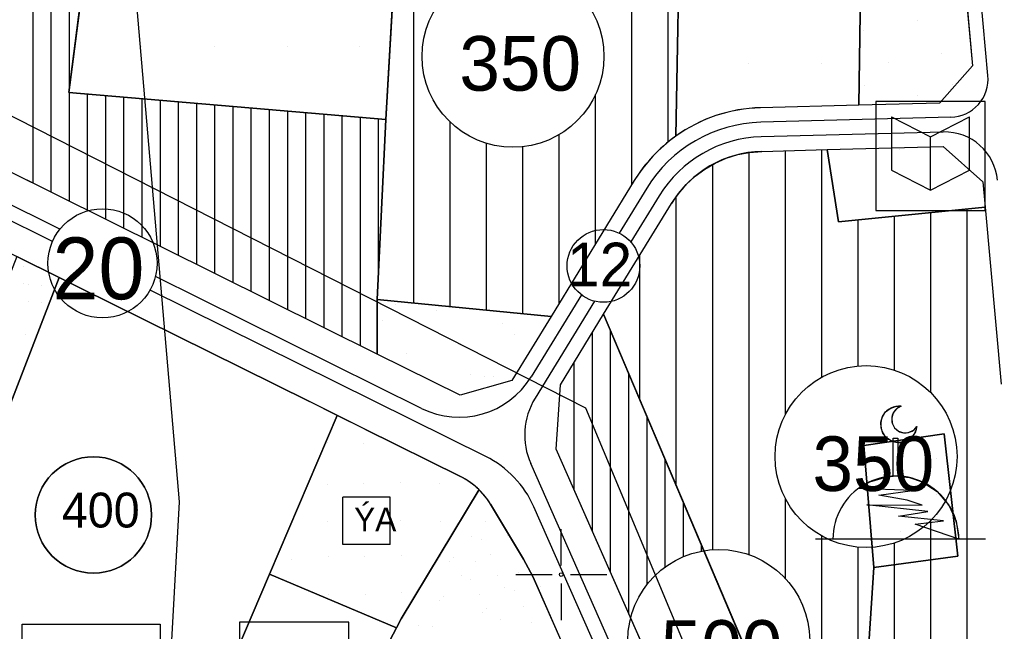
# Model space of a CAD drawing. Extents: x 419109 to 421295, y 4452223 to 4457798.
# Drawn here: x 420351.1 to 420619.9, y 4452484.4 to 4452652.5 of the extents above; entities that cross this region are included whole.
import ezdxf

# ---------------------------------------------------------------- set-up
doc = ezdxf.new("R2010")
doc.units = 0
for name, color, linetype in [('ADA', 7, 'Continuous'), ('ADAKENARI', 7, 'Continuous'), ('Default', 7, 'Continuous'), ('KALDIRIM', 7, 'Continuous'), ('KD_DAIRE', 7, 'Continuous'), ('KD_YGEN', 7, 'Continuous'), ('LJ_SEMBOL', 7, 'Continuous'), ('PAFTALAMA', 7, 'Continuous'), ('PL_AYA_PARK_DINLENME', 7, 'Continuous'), ('PL_KON_MEV_350', 7, 'Continuous'), ('PL_KON_MEV_450', 7, 'Continuous'), ('PL_KON_MEV_500', 7, 'Continuous'), ('PL_OZEL_DONATI', 7, 'Continuous'), ('PL_SAY_DINI_TESIS', 7, 'Continuous'), ('PL_SAY_ILKOGRETIM', 7, 'Continuous'), ('PL_SAY_KULTUR_TESIS', 7, 'Continuous'), ('PL_TİCK', 7, 'Continuous'), ('SM_DAIRE', 7, 'Continuous'), ('SM_SEMBOL', 7, 'Continuous'), ('SM_TAKS', 7, 'Continuous'), ('SN_3_DERECE_KAYNAK_KORUMA', 7, 'Continuous'), ('SN_KENTSEL_DONUSUM', 7, 'Continuous'), ('TR_DINITESIS', 7, 'Continuous'), ('TR_ILKEGITIM', 7, 'Continuous'), ('TR_KULTURELTESIS', 7, 'Continuous'), ('TR_ORTAYOGUNKONUT', 7, 'Continuous'), ('TR_PARKALANI', 7, 'Continuous'), ('TR_SAGLIKTESIS', 7, 'Continuous'), ('TR_TİCK', 7, 'Continuous'), ('TR_YUKSEKYOGUNKONUT', 7, 'Continuous')]:
    doc.layers.add(name, color=color, linetype=linetype)

# ---------------------------------------------------------------- blocks, each defined once
blk = doc.blocks.new('POINT_DISPLAY')
at = {"layer": 'Default'}
blk.add_line((0, 0), (0, 0), dxfattribs=at)

msp = doc.modelspace()

# ---------------------------------------------------------------- linework, layer by layer
at = {"layer": 'ADA'}
for p, q in [((420376.66, 4452726.13), (420364.66, 4452632.46)), ((420451.75, 4452625.1), (420455.62, 4452691.68)), ((420532.64, 4452685.1), (420531.45, 4452620.49)), ((420581.77, 4452629.03), (420582.63, 4452685.79)), ((420364.66, 4452632.46), (420451.75, 4452625.1)), ((420451.75, 4452625.1), (420449.42, 4452575.56)), ((420573.09, 4452616.8), (420576.19, 4452596.92)), ((420576.19, 4452596.92), (420616.56, 4452601)), ((420344.45, 4452590.34), (420367.8, 4452578.76)), ((420333.09, 4452507.03), (420361.98, 4452581.65)), ((420449.42, 4452575.56), (420497.19, 4452570.95)), ((420449.42, 4452560.62), (420449.42, 4452575.56)), ((420553.65, 4452472.53), (420511.62, 4452571.53)), ((420446, 4452539.98), (420430.76, 4452547.54)), ((420438.38, 4452543.76), (420401.24, 4452456.66)), ((420605.26, 4452538.64), (420583.2, 4452535.51)), ((420608.99, 4452505.09), (420605.26, 4452538.64)), ((420583.2, 4452535.51), (420585.88, 4452501.96)), ((420477.38, 4452523.34), (420456, 4452487.81)), ((420585.88, 4452501.96), (420608.99, 4452505.09)), ((420454.71, 4452485.36), (420419.76, 4452500.1)), ((420456, 4452487.81), (420435.44, 4452448.79))]:
    msp.add_line(p, q, dxfattribs=at)
msp.add_arc((420463.41, 4452509.02), 20, 30.9491, 63.6203, dxfattribs=at)
at = {"layer": 'ADAKENARI'}
for p, q in [((420609.16, 4452682.74), (420613.04, 4452639.84)), ((420361.09, 4452604.42), (420282.55, 4452643.37)), ((420613.04, 4452639.84), (420603.95, 4452629.61)), ((420581.77, 4452629.03), (420554.77, 4452628.32)), ((420603.95, 4452629.61), (420581.77, 4452629.03)), ((420573.09, 4452616.8), (420605.03, 4452617.64)), ((420605.03, 4452617.64), (420615.93, 4452607.94)), ((420555.09, 4452616.32), (420573.09, 4452616.8)), ((420520.07, 4452608.28), (420497.19, 4452570.95)), ((420615.93, 4452607.94), (420616.56, 4452601)), ((420449.42, 4452560.62), (420361.09, 4452604.42)), ((420511.62, 4452571.53), (420530.3, 4452602.01)), ((420616.56, 4452601), (420620.97, 4452552.31)), ((420367.8, 4452578.76), (420412.06, 4452556.81)), ((420497.19, 4452570.95), (420486.43, 4452553.38)), ((420499.75, 4452552.17), (420511.62, 4452571.53)), ((420472.24, 4452549.3), (420449.42, 4452560.62)), ((420412.06, 4452556.81), (420430.76, 4452547.54)), ((420486.43, 4452553.38), (420472.24, 4452549.3)), ((420498.57, 4452534.49), (420499.75, 4452552.17)), ((420446, 4452539.98), (420472.3, 4452526.94)), ((420569.99, 4452372.88), (420498.57, 4452534.49)), ((420480.57, 4452519.3), (420489.63, 4452504.19)), ((420489.63, 4452504.19), (420490.93, 4452501.84)), ((420490.93, 4452501.84), (420492.14, 4452499.45)), ((420492.14, 4452499.45), (420493.27, 4452497.02)), ((420493.27, 4452497.02), (420502.09, 4452477.06))]:
    msp.add_line(p, q, dxfattribs=at)
for radius, start, end in [(42, 91.5128, 125.5707), (42, 125.5707, 148.4977), (30, 91.5128, 148.4977)]:
    msp.add_arc((420555.88, 4452586.33), radius, start, end, dxfattribs=at)
at = {"layer": 'KALDIRIM'}
for p, q in [((420617.3, 4452637.2), (420613.16, 4452682.89)), ((420362.19, 4452594.94), (420278.83, 4452636.28)), ((420360.12, 4452591.51), (420277.07, 4452632.69)), ((420360.12, 4452591.51), (420278.42, 4452632.02)), ((420607.07, 4452625.7), (420554.87, 4452624.32)), ((420605.01, 4452621.64), (420554.98, 4452620.32)), ((420523.48, 4452606.19), (420515.92, 4452593.85)), ((420526.89, 4452604.1), (420519.12, 4452591.42)), ((420461.55, 4452545.67), (420388.44, 4452581.93)), ((420479.27, 4452532.42), (420386.96, 4452578.2)), ((420505.52, 4452576.89), (420491.71, 4452554.35)), ((420509.14, 4452575.14), (420492.8, 4452548.47)), ((420532.87, 4452437.08), (420491.59, 4452530.5)), ((420529.24, 4452435.4), (420492.46, 4452518.63))]:
    msp.add_line(p, q, dxfattribs=at)
for centre, radius, start, end in [((420606.79, 4452636.24), 10.55, 271.5128, 5.172), ((420555.88, 4452586.33), 38, 91.5128, 148.4977), ((420555.88, 4452586.33), 34, 91.5128, 148.4977), ((420605.4, 4452607.08), 14.57, 5.172, 91.5128), ((420471.89, 4452566.5), 23.25, 243.6241, 328.4977), ((420509.33, 4452538.33), 19.39, 148.4977, 203.8418), ((420466.81, 4452507.3), 28.04, 23.8418, 63.6241)]:
    msp.add_arc(centre, radius, start, end, dxfattribs=at)
at = {"layer": 'KD_DAIRE'}
for centre, radius in [((420373.88, 4452585.55), 15), ((420511.6, 4452584.83), 10)]:
    msp.add_circle(centre, radius, dxfattribs=at)
at = {"layer": 'LJ_SEMBOL'}
for p, q in [((420616.5, 4452630.06), (420586.5, 4452630.06)), ((420586.5, 4452630.06), (420586.5, 4452600.06)), ((420616.5, 4452600.06), (420616.5, 4452630.06)), ((420590.81, 4452625.77), (420590.81, 4452611.11)), ((420590.81, 4452625.77), (420601.5, 4452620.33)), ((420601.5, 4452620.33), (420612.19, 4452625.77)), ((420612.19, 4452611.11), (420612.19, 4452625.77)), ((420601.5, 4452605.66), (420601.5, 4452620.33)), ((420590.81, 4452611.11), (420601.5, 4452605.66)), ((420601.5, 4452605.66), (420612.19, 4452611.11)), ((420586.5, 4452600.06), (420616.5, 4452600.06)), ((420616.59, 4452509.74), (420569.93, 4452509.74))]:
    msp.add_line(p, q, dxfattribs=at)
for points in [[(420586.5, 4452600.06), (420616.5, 4452600.06), (420616.5, 4452630.06), (420586.5, 4452630.06)], [(420597.77, 4452540.7), (420597.35, 4452539.2), (420596.48, 4452537.89), (420595.25, 4452536.92), (420593.78, 4452536.38), (420592.21, 4452536.32), (420590.7, 4452536.75), (420589.4, 4452537.62), (420588.44, 4452538.86), (420587.9, 4452540.33), (420587.84, 4452541.89), (420588.27, 4452543.4), (420589.15, 4452544.7), (420590.39, 4452545.66), (420591.86, 4452546.2), (420593.43, 4452546.25), (420592.17, 4452545.55), (420591.27, 4452544.44), (420590.85, 4452543.07), (420590.98, 4452541.64), (420591.63, 4452540.37), (420592.72, 4452539.43), (420594.07, 4452538.97), (420595.5, 4452539.04), (420596.8, 4452539.65)], [(420609.29, 4452509.75), (420597.31, 4452513.81), (420605.1, 4452514.72), (420592.66, 4452516.03), (420600.75, 4452517.29), (420584, 4452519.18), (420599.25, 4452519.1), (420595.08, 4452520.42), (420587.3, 4452521.85), (420596.52, 4452523.1), (420581.63, 4452523.62), (420584.8, 4452525.5), (420589.52, 4452526.88), (420591.27, 4452527.05), (420591.27, 4452537.46), (420592.52, 4452537.46), (420592.52, 4452527.05), (420595.76, 4452526.64), (420599.17, 4452525.5), (420603.32, 4452522.83), (420606.54, 4452519.11), (420608.59, 4452514.63)], [(420351.83, 4452486.39), (420389.76, 4452486.39), (420389.76, 4452457.46), (420351.83, 4452457.46)], [(420411.55, 4452456.89), (420441.55, 4452456.89), (420441.55, 4452486.89), (420411.55, 4452486.89)]]:
    msp.add_lwpolyline(points, close=True, dxfattribs=at)
for centre, radius, start, end in [((420592.81, 4452541.29), 5, 82.8556, 353.3219), ((420594.58, 4452542.68), 3.75, 107.9671, 328.2104), ((420591.98, 4452509.75), 17.31, 359.967, 180)]:
    msp.add_arc(centre, radius, start, end, dxfattribs=at)
at = {"layer": 'PAFTALAMA'}
for p, q in [((420500, 4452502.5), (420500, 4452512.5)), ((420487.5, 4452500), (420497.5, 4452500)), ((420502.5, 4452500), (420512.5, 4452500)), ((420500, 4452497.5), (420500, 4452487.5))]:
    msp.add_line(p, q, dxfattribs=at)
msp.add_circle((420500, 4452500), 0.5, dxfattribs=at)
at = {"layer": 'PL_AYA_PARK_DINLENME'}
for points in [[(420609.16, 4452682.74), (420613.04, 4452639.84), (420603.95, 4452629.61), (420581.77, 4452629.03), (420582.63, 4452685.79)], [(420449.42, 4452575.56), (420497.19, 4452570.95), (420486.43, 4452553.38), (420472.24, 4452549.3), (420449.42, 4452560.62)]]:
    msp.add_lwpolyline(points, close=True, dxfattribs=at)
for points in [[(420264.82, 4452450.42), (420276.25, 4452443.66), (420320.59, 4452492), (420333.09, 4452507.03), (420361.98, 4452581.65), (420350.28, 4452587.45), (420350.28, 4452587.45), (420321.86, 4452514.01), (420315.23, 4452506.09), (420308.58, 4452498.14), (420264.82, 4452450.42)], [(420477.38, 4452523.34), (420456, 4452487.81), (420454.71, 4452485.36), (420435.44, 4452448.79), (420430.68, 4452439.74), (420426.62, 4452432.05), (420521.98, 4452432.05), (420521.98, 4452432.05), (420508.96, 4452461.5), (420502.09, 4452477.06), (420493.27, 4452497.02), (420492.14, 4452499.45), (420490.93, 4452501.84), (420489.63, 4452504.19), (420480.57, 4452519.3)]]:
    msp.add_lwpolyline(points, dxfattribs=at)
msp.add_arc((420463.41, 4452509.02), 20, 30.9491, 45.7214, dxfattribs=at)
at = {"layer": 'PL_KON_MEV_350'}
msp.add_lwpolyline([(420520.07, 4452608.28), (420497.19, 4452570.95), (420449.42, 4452575.56), (420451.75, 4452625.1), (420455.62, 4452691.68), (420520.57, 4452686.13), (420532.64, 4452685.1), (420531.45, 4452620.49), (420529.77, 4452619.23), (420528.16, 4452617.88), (420526.61, 4452616.46), (420525.14, 4452614.96), (420523.75, 4452613.38), (420522.44, 4452611.74), (420521.21, 4452610.04)], close=True, dxfattribs=at)
for points in [[(420553.65, 4452472.53), (420511.62, 4452571.53), (420530.3, 4452602.01), (420532.18, 4452604.73), (420534.36, 4452607.23), (420536.79, 4452609.48), (420539.46, 4452611.44), (420542.33, 4452613.1), (420545.37, 4452614.43), (420548.53, 4452615.42), (420551.78, 4452616.05), (420555.09, 4452616.32), (420573.09, 4452616.8), (420576.19, 4452596.92), (420616.56, 4452601), (420620.97, 4452552.31)], [(420584.26, 4452476.75), (420585.88, 4452501.96), (420608.99, 4452505.09), (420605.26, 4452538.64), (420583.2, 4452535.51), (420585.88, 4452501.96), (420584.26, 4452476.75)]]:
    msp.add_lwpolyline(points, dxfattribs=at)
at = {"layer": 'PL_KON_MEV_450'}
msp.add_lwpolyline([(420299.79, 4452788.55), (420467.87, 4452834.02), (420464.63, 4452792.44), (420385.14, 4452799.11), (420376.66, 4452726.13), (420364.66, 4452632.46), (420451.75, 4452625.1), (420449.42, 4452575.56), (420449.42, 4452560.62), (420361.09, 4452604.42), (420282.55, 4452643.37), (420274.78, 4452657.74), (420288.95, 4452776.01)], close=True, dxfattribs=at)
at = {"layer": 'PL_KON_MEV_500'}
msp.add_lwpolyline([(420569.99, 4452372.88), (420498.57, 4452534.49), (420499.75, 4452552.17), (420511.62, 4452571.53), (420553.65, 4452472.53), (420592.92, 4452383.64)], close=True, dxfattribs=at)
at = {"layer": 'PL_OZEL_DONATI'}
msp.add_lwpolyline([(420532.64, 4452685.1), (420554.32, 4452686.65), (420582.63, 4452685.79), (420581.77, 4452629.03), (420554.77, 4452628.32), (420551.66, 4452628.12), (420548.57, 4452627.69), (420545.52, 4452627.03), (420542.52, 4452626.15), (420539.6, 4452625.05), (420536.77, 4452623.73), (420534.05, 4452622.21), (420531.45, 4452620.49)], close=True, dxfattribs=at)
at = {"layer": 'PL_SAY_DINI_TESIS'}
msp.add_lwpolyline([(420472.3, 4452526.94), (420446, 4452539.98), (420438.38, 4452543.76), (420419.76, 4452500.1), (420454.71, 4452485.36), (420456, 4452487.81), (420477.38, 4452523.34)], dxfattribs=at)
msp.add_lwpolyline([(420585.88, 4452501.96), (420583.2, 4452535.51), (420605.26, 4452538.64), (420608.99, 4452505.09)], close=True, dxfattribs=at)
msp.add_arc((420463.41, 4452509.02), 20, 45.7214, 63.6203, dxfattribs=at)
at = {"layer": 'PL_SAY_ILKOGRETIM'}
msp.add_lwpolyline([(420364.66, 4452632.46), (420376.66, 4452726.13), (420457.13, 4452717.64), (420455.62, 4452691.68), (420451.75, 4452625.1)], close=True, dxfattribs=at)
at = {"layer": 'PL_SAY_KULTUR_TESIS'}
msp.add_lwpolyline([(420616.56, 4452601), (420576.19, 4452596.92), (420573.09, 4452616.8), (420605.03, 4452617.64), (420615.93, 4452607.94)], close=True, dxfattribs=at)
msp.add_lwpolyline([(420454.71, 4452485.36), (420419.76, 4452500.1), (420401.24, 4452456.66), (420430.68, 4452439.74), (420435.44, 4452448.79), (420454.71, 4452485.36)], dxfattribs=at)
at = {"layer": 'PL_TİCK'}
msp.add_lwpolyline([(420276.25, 4452443.66), (420281.87, 4452440.33), (420366.31, 4452390.34), (420401.24, 4452456.66), (420419.76, 4452500.1), (420438.38, 4452543.76), (420430.76, 4452547.54), (420412.06, 4452556.81), (420367.8, 4452578.76), (420361.98, 4452581.65), (420333.09, 4452507.03), (420320.59, 4452492), (420276.25, 4452443.66)], dxfattribs=at)
at = {"layer": 'SM_DAIRE'}
for centre in [(420486.72, 4452642.44), (420583.79, 4452532.43), (420543.3, 4452481.88)]:
    msp.add_circle(centre, 25, dxfattribs=at)
at = {"layer": 'SM_SEMBOL'}
for points in [[(420452.93, 4452521.26), (420439.93, 4452521.26)], [(420439.93, 4452508.26), (420439.93, 4452521.26)], [(420452.93, 4452508.26), (420452.93, 4452521.26)], [(420452.93, 4452508.26), (420439.93, 4452508.26)]]:
    msp.add_lwpolyline(points, dxfattribs=at)
at = {"layer": 'SM_TAKS'}
msp.add_circle((420371.38, 4452516.37), 15.99, dxfattribs=at)
at = {"layer": 'SN_3_DERECE_KAYNAK_KORUMA'}
msp.add_lwpolyline([(420357.81, 4452232.59), (420364.57, 4452258.77), (420388.14, 4452395.87), (420395.04, 4452520.02), (420383.4, 4452655.62), (420344.11, 4452773.22), (420290.77, 4452875.07), (420213.22, 4452980.45), (420010.57, 4453225.26), (419772.92, 4453473.96), (419554.68, 4453657.1), (419332.55, 4453805.23), (419159.82, 4453894.89), (419126.5, 4453906.07)], dxfattribs=at)
at = {"layer": 'SN_KENTSEL_DONUSUM'}
for p, q in [((420285.4, 4452658.29), (420506.7, 4452545.79)), ((420506.7, 4452545.79), (420589.68, 4452346.63))]:
    msp.add_line(p, q, dxfattribs=at)
at = {"layer": 'TR_ORTAYOGUNKONUT'}
for p, q in [((420459.42, 4452574.59), (420459.42, 4452691.35)), ((420519.42, 4452607.22), (420519.42, 4452686.23)), ((420529.42, 4452618.94), (420529.42, 4452685.37)), ((420509.42, 4452590.91), (420509.42, 4452631.99)), ((420469.42, 4452573.63), (420469.42, 4452624.39)), ((420499.42, 4452574.59), (420499.42, 4452620.91)), ((420479.42, 4452572.66), (420479.42, 4452618.53)), ((420489.42, 4452571.7), (420489.42, 4452617.59)), ((420551.62, 4452505.45), (420551.62, 4452616.02)), ((420561.62, 4452543.99), (420561.62, 4452616.49)), ((420571.62, 4452554.27), (420571.62, 4452616.76)), ((420541.62, 4452506.83), (420541.62, 4452612.69)), ((420531.62, 4452524.42), (420531.62, 4452603.92)), ((420601.62, 4452549.95), (420601.62, 4452599.49)), ((420611.62, 4452392.41), (420611.62, 4452600.5)), ((420581.62, 4452557.33), (420581.62, 4452597.47)), ((420591.62, 4452556.17), (420591.62, 4452598.48)), ((420521.62, 4452547.98), (420521.62, 4452587.85)), ((420561.62, 4452498.89), (420561.62, 4452520.86)), ((420601.62, 4452404.62), (420601.62, 4452514.91)), ((420571.62, 4452475), (420571.62, 4452510.59)), ((420581.62, 4452476.38), (420581.62, 4452507.52)), ((420591.62, 4452446.16), (420591.62, 4452508.69))]:
    msp.add_line(p, q, dxfattribs=at)
at = {"layer": 'TR_TİCK'}
for points in [[(420361.98, 4452581.65), (420333.09, 4452507.03), (420320.59, 4452492), (420276.25, 4452443.66), (420281.87, 4452440.33), (420366.31, 4452390.34), (420401.24, 4452456.66), (420419.76, 4452500.1), (420438.38, 4452543.76), (420430.76, 4452547.54), (420412.06, 4452556.81), (420367.8, 4452578.76), (420361.98, 4452581.65)], [(420351.83, 4452457.46), (420351.83, 4452486.39), (420389.76, 4452486.39), (420389.76, 4452457.46), (420351.83, 4452457.46)]]:
    msp.add_lwpolyline(points, dxfattribs=at)
for start, end in [(0, 180), (180, 0)]:
    msp.add_arc((420371.38, 4452516.37), 15.99, start, end, dxfattribs=at)
at = {"layer": 'TR_YUKSEKYOGUNKONUT'}
for p, q in [((420364.78, 4452633.41), (420364.78, 4452806.13)), ((420354.78, 4452607.55), (420354.78, 4452803.43)), ((420359.78, 4452605.07), (420359.78, 4452804.78)), ((420364.78, 4452602.59), (420364.78, 4452632.45)), ((420369.78, 4452600.11), (420369.78, 4452632.02)), ((420374.78, 4452597.63), (420374.78, 4452631.6)), ((420379.78, 4452595.15), (420379.78, 4452631.18)), ((420384.78, 4452592.67), (420384.78, 4452630.76)), ((420389.78, 4452590.19), (420389.78, 4452630.33)), ((420394.78, 4452587.71), (420394.78, 4452629.91)), ((420399.78, 4452585.23), (420399.78, 4452629.49)), ((420404.78, 4452582.75), (420404.78, 4452629.07)), ((420409.78, 4452580.27), (420409.78, 4452628.65)), ((420414.78, 4452577.8), (420414.78, 4452628.22)), ((420419.78, 4452575.32), (420419.78, 4452627.8)), ((420424.78, 4452572.84), (420424.78, 4452627.38)), ((420429.78, 4452570.36), (420429.78, 4452626.96)), ((420434.78, 4452567.88), (420434.78, 4452626.53)), ((420439.78, 4452565.4), (420439.78, 4452626.11)), ((420444.78, 4452562.92), (420444.78, 4452625.69)), ((420449.78, 4452583.13), (420449.78, 4452625.27)), ((420508.57, 4452511.87), (420508.57, 4452566.55)), ((420513.57, 4452500.55), (420513.57, 4452566.95)), ((420503.57, 4452523.18), (420503.57, 4452558.39)), ((420518.57, 4452489.24), (420518.57, 4452555.17)), ((420523.57, 4452497.24), (420523.57, 4452543.39)), ((420528.57, 4452502.09), (420528.57, 4452531.61)), ((420533.57, 4452504.91), (420533.57, 4452519.83)), ((420538.57, 4452506.43), (420538.57, 4452508.06))]:
    msp.add_line(p, q, dxfattribs=at)

# ---------------------------------------------------------------- block references
at = {"layer": 'TR_DINITESIS', "xscale": 0.1, "yscale": 0.10000000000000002}
for p in [(420435.74, 4452536.3), (420445.5, 4452536.11), (420593.2, 4452531.96), (420603.2, 4452531.96), (420435.74, 4452524.84), (420445.5, 4452524.93), (420455.83, 4452525.21), (420466.48, 4452525.09), (420593.2, 4452521.96), (420603.2, 4452521.96), (420435.74, 4452514.5), (420445.88, 4452514.5), (420455.83, 4452514.98), (420466.86, 4452514.67), (420593.2, 4452511.96), (420603.2, 4452511.96), (420436.06, 4452504.83), (420445.83, 4452504.93), (420456.16, 4452505.21), (420466.8, 4452505.09), (420425.81, 4452504.01), (420436.12, 4452494.59), (420446.26, 4452494.59), (420456.21, 4452495.07)]:
    msp.add_blockref('POINT_DISPLAY', p, dxfattribs=at)
at = {"layer": 'TR_ILKEGITIM', "xscale": 0.1, "yscale": 0.10000000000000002}
for p in [(420384.66, 4452645.1), (420404.66, 4452645.1), (420424.66, 4452645.1), (420444.66, 4452645.1)]:
    msp.add_blockref('POINT_DISPLAY', p, dxfattribs=at)
at = {"layer": 'TR_KULTURELTESIS', "xscale": 0.1, "yscale": 0.10000000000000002}
msp.add_blockref('POINT_DISPLAY', (420593.09, 4452616.92), dxfattribs=at)
at = {"layer": 'TR_PARKALANI', "xscale": 0.1, "yscale": 0.10000000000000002}
for p in [(420597.99, 4452652.2), (420583.22, 4452649.59), (420604.65, 4452643.22), (420589.88, 4452640.61), (420583.29, 4452634.33), (420607.42, 4452634.71), (420598.06, 4452631.73), (420352.28, 4452584.65), (420352.28, 4452580.06), (420353.45, 4452579.75), (420357.2, 4452579.41), (420353.45, 4452575.16), (420357.2, 4452574.82), (420454.42, 4452574.3), (420465.65, 4452572.47), (420450.87, 4452569.86), (420483.97, 4452569.09), (420352.61, 4452566.06), (420487.08, 4452566.09), (420472.31, 4452563.49), (420457.54, 4452560.88), (420475.08, 4452554.98), (420478.97, 4452554.51), (420481.36, 4452554.32), (420479.21, 4452514.58), (420475.34, 4452510.53), (420485.35, 4452510.71), (420477.98, 4452509.66), (420470.41, 4452504.76), (420480.46, 4452505.44), (420469.33, 4452503.64), (420476.39, 4452503.67), (420472.52, 4452499.62), (420482.53, 4452499.8), (420488.24, 4452500.48), (420475.16, 4452498.75), (420494.38, 4452496.61), (420477.64, 4452494.54), (420484.36, 4452496.43), (420487.01, 4452495.56), (420466.51, 4452492.74), (420467.58, 4452493.85), (420489.49, 4452491.34), (420478.36, 4452489.54), (420479.43, 4452490.65), (420460.87, 4452485.97), (420483.28, 4452487.77), (420491.71, 4452486.72), (420464.62, 4452485.63)]:
    msp.add_blockref('POINT_DISPLAY', p, dxfattribs=at)
at = {"layer": 'TR_SAGLIKTESIS', "xscale": 0.1, "yscale": 0.10000000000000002}
for p in [(420551.45, 4452640.49), (420571.45, 4452640.49)]:
    msp.add_blockref('POINT_DISPLAY', p, dxfattribs=at)

# ---------------------------------------------------------------- texts
at = {"layer": 'KD_YGEN'}
for s, height, p in [('20', 17, (420360.12, 4452575.65)), ('12', 12, (420501.63, 4452579.22))]:
    msp.add_text(s, height=height, dxfattribs=at).set_placement(p)
at = {"layer": 'SM_SEMBOL'}
msp.add_text('ÝA', height=6.5, dxfattribs=at).set_placement((420443.05, 4452511.9))
at = {"layer": 'SM_TAKS'}
for s, height, p in [('350', 15, (420471.97, 4452633)), ('350', 15, (420569.05, 4452522.98)), ('400', 9.593, (420362.69, 4452512.92)), ('500', 15, (420527.31, 4452472.44))]:
    msp.add_text(s, height=height, dxfattribs=at).set_placement(p)

doc.saveas('drawing.dxf')
